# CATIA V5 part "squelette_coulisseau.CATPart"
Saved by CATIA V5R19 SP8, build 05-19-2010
Part number: squelette_coulisseau
Publications: "Plan.1", "Droite.1", "Plan.3", "Plan.4"
Bounding box of the stored display mesh (mm): x 27.851 to 83, y 155.273 to 340.099, z 65.101 to 113.864
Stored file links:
  G:\EU_thinkMotion\CFAO_2010\MMS_groupe3\MMS_groupe3\A reprendre\amenand\amenand\squelette_coulisseau.CATPart
  F:\thinkmotion CFAO v12.1\essuie_glace.CATProduct
  G:\EU_thinkMotion\CFAO_2010\MMS_groupe3\MMS_groupe3\A reprendre\amenand\amenand\squelette_couronne.CATPart
  G:\EU_thinkMotion\CFAO_2010\MMS_groupe3\MMS_groupe3\A reprendre\amenand\amenand\balancier.CATPart
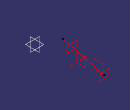
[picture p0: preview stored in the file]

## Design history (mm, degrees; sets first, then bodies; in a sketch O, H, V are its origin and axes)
Set1
  Plane1: linked copy from another document
  Point1: linked copy from another document
  Point2: linked copy from another document
Set2 "set géométrique.9"
  Plane2: type Offset, RefPlane Plane1, Offset 16, reversed
  Point3: type OnPlane, Support Plane2, H 340.099, V 65.101, Direction (0, 1, 0)
  Point4: type OnPlane, Support Plane2, RefPoint Point1, H 0, V 0, Direction (0, 1, 0)
  Line1: type PtPt, FirstPoint Point3, SecondPoint Point4, End 100
  Plane3: type Normal, Curve Line1, RefPoint Point3
  Plane4: type Offset, RefPlane Plane3, Offset 150
  Point5: type OnCurve, Support Line1, RefPoint Point2, Length 0
Body1 (main body)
